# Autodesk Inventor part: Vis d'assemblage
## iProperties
Shininess: 64.0
Length Units: 11269
Angle Units: 11279
Time Units: 11290
Mass Units: 11283
Length Display Precision: 3
Angle Display Precision: 2
Compacted: True
Part Number: Vis d'assemblage
Document SubType Name: Modeling
Created: 2005-01
Material: Par défaut
Designer: lolo (Laurent Moretti)
Density: 0.0
Volumn: 0.0
Area: 0.0
PropertySet Name: Model Information
Control State: 0
Master: False
Checked Out: False
Author: lolo (Laurent Moretti)
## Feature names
1. Révolution1 [Revolution]
2. Chanfrein1 [Chamfer]
3. Chanfrein2 [Chamfer]
4. Extrusion1
